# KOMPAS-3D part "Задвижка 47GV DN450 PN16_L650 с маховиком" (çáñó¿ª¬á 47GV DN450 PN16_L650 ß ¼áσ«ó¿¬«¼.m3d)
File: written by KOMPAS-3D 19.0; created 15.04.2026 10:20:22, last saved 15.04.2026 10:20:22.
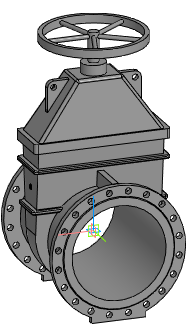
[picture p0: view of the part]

Document properties: Автор: Евгений; Полное имя файла: Z:\3.Личные\kachalov\3d для проектировщиков\2.1 Тип 47GV, 47GV.Z\Задвижка 47GV_DN40-DN600\stp_Задвижка 47GV\Задвижка 47GV DN450 PN16_L650 с маховиком.m3d

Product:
- Part/product: Задвижка 47GV DN450 PN16_L650 с маховиком

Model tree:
1. Операция без истории:1  (labels: Задвижка 47GV DN450 PN16_L650 с маховиком)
